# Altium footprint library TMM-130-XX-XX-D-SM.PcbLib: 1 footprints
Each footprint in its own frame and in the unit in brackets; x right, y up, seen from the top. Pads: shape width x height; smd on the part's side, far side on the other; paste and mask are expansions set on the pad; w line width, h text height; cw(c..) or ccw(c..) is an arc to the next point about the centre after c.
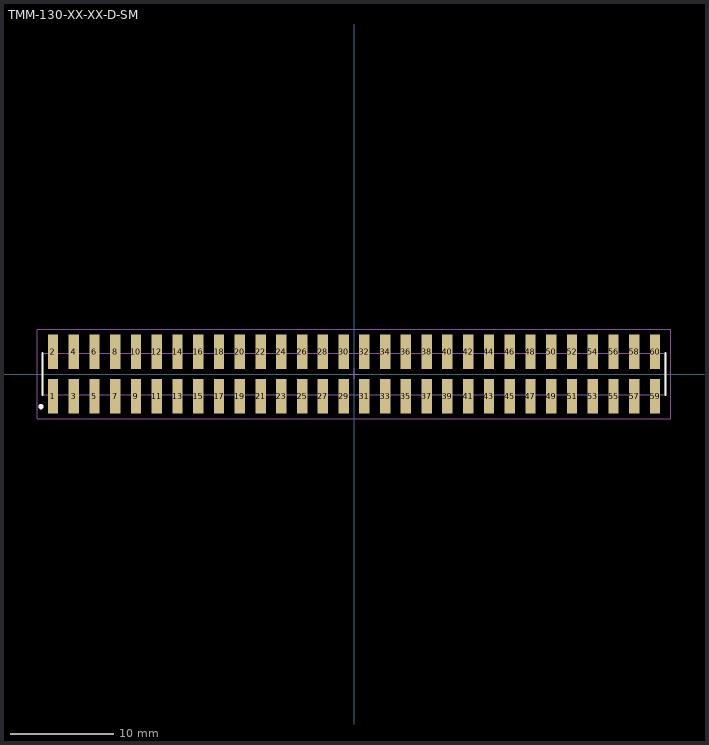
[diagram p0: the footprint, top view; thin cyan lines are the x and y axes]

## TMM-130-XX-XX-D-SM [mm] "2.00mm pitch, 60 pin, terminal strip; double row, SMT"
height 2.77
pads (60):
  rect 1x3.3 smd mask+0: 1(-29,-2.15) 2(-29,2.15) 3(-27,-2.15) 4(-27,2.15) 5(-25,-2.15) 6(-25,2.15) 7(-23,-2.15) 8(-23,2.15) 9(-21,-2.15) 10(-21,2.15) 11(-19,-2.15) 12(-19,2.15) 13(-17,-2.15) 14(-17,2.15) 15(-15,-2.15) 16(-15,2.15) 17(-13,-2.15) 18(-13,2.15) 19(-11,-2.15) 20(-11,2.15) 21(-9,-2.15) 22(-9,2.15) 23(-7,-2.15) 24(-7,2.15) 25(-5,-2.15) 26(-5,2.15) 27(-3,-2.15) 28(-3,2.15) 29(-1,-2.15) 30(-1,2.15) 31(1,-2.15) 32(1,2.15) 33(3,-2.15) 34(3,2.15) 35(5,-2.15) 36(5,2.15) 37(7,-2.15) 38(7,2.15) 39(9,-2.15) 40(9,2.15) 41(11,-2.15) 42(11,2.15) 43(13,-2.15) 44(13,2.15) 45(15,-2.15) 46(15,2.15) 47(17,-2.15) 48(17,2.15) 49(19,-2.15) 50(19,2.15) 51(21,-2.15) 52(21,2.15) 53(23,-2.15) 54(23,2.15) 55(25,-2.15) 56(25,2.15) 57(27,-2.15) 58(27,2.15) 59(29,-2.15) 60(29,2.15)
Top Overlay:
  circle w0.25: c-30.15,-3.15 r0.125
  lines w0.2: -30,-2 -30,2 ; 30,-2 30,2
Mechanical 12:
  lines w0.001: -30,-2 30,-2 30,2 -30,2 -30,-2
Mechanical 13:
  lines w0.1: -30,-2 30,-2 30,2 -30,2 -30,-2
  text ".Designator" at 0,-0.127 h1.52
Mechanical 15:
  lines w0.05: -0.5,0 0.5,0 ; 0,-0.5 0,0.5 ; -30.5,-4.3 30.5,-4.3 30.5,4.3 -30.5,4.3 -30.5,-4.3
